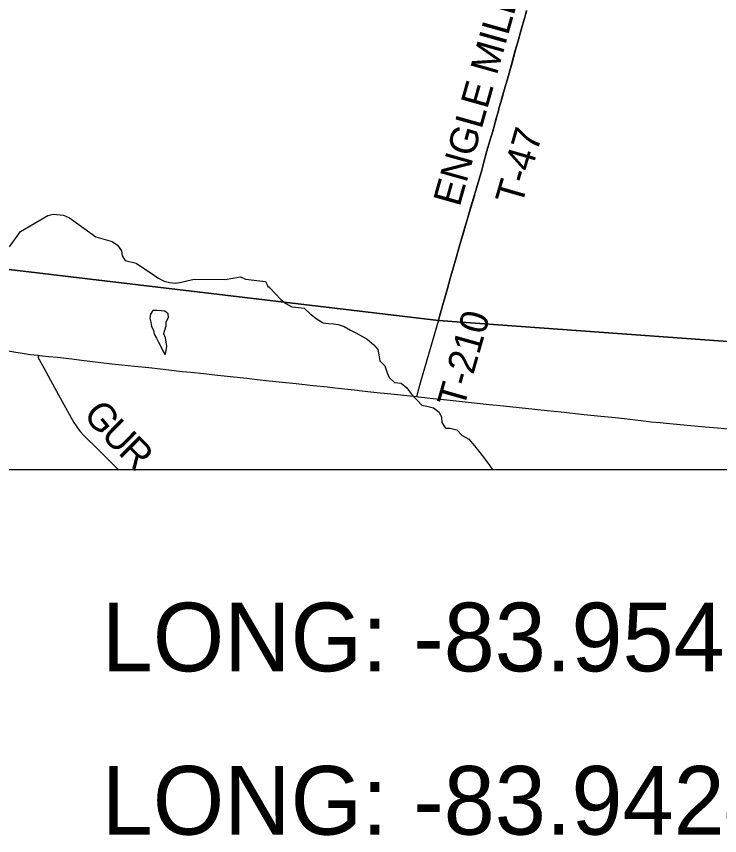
# Model space of a CAD drawing. Extents: x 0 to 34, y 0 to 22.
# Drawn here: x 12.815 to 14.248, y 13.559 to 15.23 of the extents above; entities that cross this region are included whole.
import ezdxf

# ---------------------------------------------------------------- set-up
doc = ezdxf.new("R2010")
doc.units = 0
for name, color, linetype in [('GM_X_Corporation', 7, 'Continuous'), ('GM_X_County_Road', 7, 'Continuous'), ('GM_X_County_Road_Text', 7, 'Continuous'), ('GM_X_Minor_Lake', 7, 'Continuous'), ('GM_X_Minor_River', 7, 'Continuous'), ('GM_X_Township_Road', 7, 'Continuous'), ('GM_X_Township_Road_Text', 7, 'Continuous'), ('SH_Text', 7, 'Continuous')]:
    doc.layers.add(name, color=color, linetype=linetype)

msp = doc.modelspace()

# ---------------------------------------------------------------- linework, layer by layer
at = {"layer": 'GM_X_Corporation'}
for points in [[(16.3375, 14.3932), (16.3375, 21.1059), (9.5375, 21.1059), (9.5375, 15.0426), (9.5452, 15.0418), (9.7185, 15.0258), (10.2502, 14.9799), (10.3112, 14.9746), (10.787, 14.9212), (11.3129, 14.8754), (11.3292, 14.8742), (12.1361, 14.7923), (13.6754, 14.6095), (14.714, 14.5341), (15.778, 14.4476), (16.0263, 14.4243)], [(10.7302, 14.3059), (16.3375, 14.3059), (16.3375, 14.3932), (16.0263, 14.4243), (15.778, 14.4476), (14.714, 14.5341), (13.6754, 14.6095), (12.1361, 14.7923), (11.3292, 14.8742), (11.3129, 14.8754), (10.787, 14.9212)], [(10.7302, 14.3059), (15.7632, 14.3059), (15.778, 14.4476), (14.714, 14.5341), (13.6754, 14.6095), (12.1361, 14.7923), (11.3292, 14.8742), (11.3129, 14.8754), (10.787, 14.9212)]]:
    msp.add_lwpolyline(points, close=True, dxfattribs=at)
for points in [[(12.1361, 14.7923), (13.6754, 14.6095), (13.6783, 14.6204), (13.6938, 14.6747), (13.6993, 14.6952), (13.7114, 14.7375), (13.717, 14.7569), (13.7274, 14.7926), (13.7338, 14.8149), (13.7418, 14.8415), (13.7492, 14.866), (13.7531, 14.8798), (13.7582, 14.8977), (13.7636, 14.9165), (13.7679, 14.9324), (13.7741, 14.9554), (13.7802, 14.976), (13.7861, 14.9957), (13.7895, 15.0079), (13.7928, 15.0196), (13.7976, 15.0375), (13.7988, 15.0419), (13.7995, 15.0445), (13.8005, 15.0482), (13.8016, 15.0517), (13.803, 15.0563), (13.8043, 15.0609), (13.8068, 15.0697), (13.8076, 15.0727), (13.8102, 15.0817), (13.8129, 15.0911), (13.8153, 15.0999), (13.8194, 15.1141), (13.8246, 15.1317), (13.8321, 15.1603), (13.8377, 15.1799), (13.8427, 15.1974), (13.8468, 15.2117), (13.8507, 15.2254), (13.8551, 15.2416)], [(13.8551, 15.2416), (13.8507, 15.2254), (13.8468, 15.2117), (13.8427, 15.1974), (13.8377, 15.1799), (13.8321, 15.1603), (13.8246, 15.1317), (13.8194, 15.1141), (13.8153, 15.0999), (13.8129, 15.0911), (13.8102, 15.0817), (13.8076, 15.0727), (13.8068, 15.0697), (13.8043, 15.0609), (13.803, 15.0563), (13.8016, 15.0517), (13.8005, 15.0482), (13.7995, 15.0445), (13.7988, 15.0419), (13.7976, 15.0375), (13.7928, 15.0196), (13.7895, 15.0079), (13.7861, 14.9957), (13.7802, 14.976), (13.7741, 14.9554), (13.7679, 14.9324), (13.7636, 14.9165), (13.7582, 14.8977), (13.7531, 14.8798), (13.7492, 14.866), (13.7418, 14.8415), (13.7338, 14.8149), (13.7274, 14.7926), (13.717, 14.7569), (13.7114, 14.7375), (13.6993, 14.6952), (13.6938, 14.6747), (13.6783, 14.6204), (13.6754, 14.6095), (14.714, 14.5341)]]:
    msp.add_lwpolyline(points, dxfattribs=at)
at = {"layer": 'GM_X_County_Road'}
for points in [[(12.6186, 14.5806), (12.6396, 14.5766), (12.6678, 14.5715), (12.702, 14.5654), (12.7197, 14.562), (12.7503, 14.5564), (12.8102, 14.546), (12.8317, 14.5423), (12.8434, 14.5405), (12.8595, 14.5387)], [(12.8595, 14.5387), (12.8625, 14.5383), (12.8811, 14.5364), (12.899, 14.5346), (12.9286, 14.5313), (12.9483, 14.529), (12.9876, 14.5242), (13.01, 14.5216), (13.0303, 14.5195), (13.0563, 14.5167), (13.0853, 14.5137), (13.1094, 14.5109), (13.1372, 14.5078), (13.1532, 14.506), (13.1711, 14.5041), (13.1977, 14.5013), (13.2255, 14.4983), (13.2848, 14.4919), (13.3058, 14.4897), (13.3305, 14.4868), (13.3508, 14.4845), (13.3855, 14.4809), (13.42, 14.4771), (13.4491, 14.4741), (13.4645, 14.4724), (13.5047, 14.4682), (13.5201, 14.4665), (13.538, 14.4645), (13.5565, 14.4625), (13.5652, 14.4615), (13.5856, 14.4593), (13.6177, 14.4559), (13.6312, 14.4545)], [(12.8595, 14.5387), (12.8599, 14.535), (12.8602, 14.5332), (12.8608, 14.5317), (12.8627, 14.5285), (12.8712, 14.5131), (12.8939, 14.4717), (12.9121, 14.4385), (12.9265, 14.4124), (12.9328, 14.4017), (12.9371, 14.395), (12.9414, 14.3889), (12.9464, 14.3826), (12.9525, 14.3757), (12.9612, 14.3669), (12.9745, 14.3538), (12.9963, 14.3325), (13.0227, 14.3059)], [(13.6312, 14.4545), (13.635, 14.4541), (13.6646, 14.4508), (13.6992, 14.4471), (13.7486, 14.4417), (13.7789, 14.4385), (13.8079, 14.4355), (13.8722, 14.4289), (13.8969, 14.4262), (13.9253, 14.4232), (13.9722, 14.4182), (14.0062, 14.4148), (14.0365, 14.4117), (14.0538, 14.4098), (14.0883, 14.4057), (14.1093, 14.4033), (14.1272, 14.4014), (14.1396, 14.4003), (14.1538, 14.3989), (14.1897, 14.3956), (14.2188, 14.3932), (14.2448, 14.3909), (14.2652, 14.389)]]:
    msp.add_lwpolyline(points, dxfattribs=at)
at = {"layer": 'GM_X_Minor_Lake'}
for points in [[(13.1168, 14.5859), (13.1206, 14.5989), (13.1204, 14.6073), (13.1251, 14.6155), (13.1245, 14.6231), (13.1178, 14.6286), (13.1102, 14.6295), (13.1019, 14.6304), (13.0935, 14.6302), (13.0888, 14.6223), (13.0871, 14.6144), (13.0892, 14.606), (13.091, 14.5983), (13.0946, 14.5892), (13.096, 14.5819)], [(13.096, 14.5819), (13.1008, 14.5735), (13.1048, 14.5658), (13.1099, 14.5566), (13.1139, 14.5481), (13.1187, 14.5397), (13.1208, 14.5487), (13.1217, 14.5571), (13.1207, 14.5658), (13.119, 14.5746), (13.1157, 14.5823), (13.1168, 14.5859)]]:
    msp.add_lwpolyline(points, dxfattribs=at)
at = {"layer": 'GM_X_Minor_River'}
for points in [[(12.8017, 14.7599), (12.8236, 14.791), (12.8793, 14.8235), (12.8904, 14.8263), (12.9112, 14.8246), (12.924, 14.819), (12.977, 14.7802), (13.0106, 14.7706), (13.0218, 14.7631), (13.0299, 14.7515), (13.0309, 14.7416), (13.0371, 14.732), (13.0598, 14.7265), (13.0971, 14.7016)], [(13.0971, 14.7016), (13.104, 14.6969), (13.1164, 14.6902), (13.1277, 14.6873), (13.1394, 14.6859), (13.1516, 14.6876), (13.1653, 14.6911), (13.1753, 14.6935), (13.1804, 14.6941)], [(13.1804, 14.6941), (13.2412, 14.6934), (13.272, 14.6987), (13.2822, 14.6939), (13.3234, 14.6892), (13.3273, 14.6808)], [(13.3266, 14.6808), (13.3321, 14.6764), (13.3433, 14.664), (13.3544, 14.6524), (13.3645, 14.6442), (13.3769, 14.6375), (13.3902, 14.6361), (13.4019, 14.6347), (13.4142, 14.6234), (13.4284, 14.6125), (13.4408, 14.6051), (13.4514, 14.6037), (13.4616, 14.6027), (13.4715, 14.6014), (13.4832, 14.5977), (13.496, 14.5903), (13.5072, 14.5847), (13.5208, 14.5772), (13.5305, 14.5717), (13.544, 14.5604), (13.5521, 14.5504), (13.5538, 14.5397), (13.5558, 14.5272), (13.5663, 14.5171), (13.5713, 14.5033), (13.5753, 14.4937), (13.5861, 14.4832), (13.5997, 14.4822), (13.6109, 14.4725), (13.6202, 14.4605), (13.6306, 14.4489), (13.6418, 14.4373), (13.652, 14.4348), (13.6656, 14.4319), (13.6772, 14.4229), (13.6819, 14.4126), (13.6824, 14.4019), (13.6902, 14.3904), (13.6997, 14.3902), (13.7133, 14.3865), (13.7237, 14.3753), (13.7376, 14.3674), (13.7491, 14.3542), (13.7569, 14.3442), (13.7643, 14.3342), (13.7754, 14.3199), (13.785, 14.3068), (13.7854, 14.3059)]]:
    msp.add_lwpolyline(points, dxfattribs=at)
at = {"layer": 'GM_X_Township_Road'}
for points in [[(13.8504, 15.223), (13.8509, 15.2248), (13.8553, 15.241)], [(13.6756, 14.6089), (13.6785, 14.6198), (13.6941, 14.6742), (13.6995, 14.6946), (13.7116, 14.737), (13.7172, 14.7563), (13.7276, 14.7921), (13.734, 14.8144), (13.742, 14.841), (13.7495, 14.8655), (13.7534, 14.8793), (13.7585, 14.8972), (13.7638, 14.9159), (13.7681, 14.9318), (13.7743, 14.9548), (13.7805, 14.9755), (13.7863, 14.9952), (13.7898, 15.0074), (13.7931, 15.0191), (13.7979, 15.0369), (13.7991, 15.0414), (13.7997, 15.044), (13.8007, 15.0476), (13.8018, 15.0512), (13.8032, 15.0558), (13.8046, 15.0603), (13.8071, 15.0692), (13.8079, 15.0722), (13.8104, 15.0812), (13.8131, 15.0905), (13.8155, 15.0994), (13.8196, 15.1136), (13.8248, 15.1311), (13.8323, 15.1597), (13.8379, 15.1794), (13.8429, 15.1969), (13.847, 15.2112), (13.8504, 15.223)], [(13.6312, 14.4545), (13.6355, 14.4704), (13.6398, 14.4854), (13.6511, 14.5248), (13.6727, 14.5997), (13.6756, 14.6089)]]:
    msp.add_lwpolyline(points, dxfattribs=at)

# ---------------------------------------------------------------- texts
at = {"layer": 'GM_X_County_Road_Text'}
for s, rotation, p in [('G', 309.2165, (12.9498, 14.4176)), ('U', 315.1567, (12.9857, 14.3741)), ('R', 314.9338, (13.0211, 14.3389))]:
    msp.add_text(s, height=0.0568, rotation=rotation, dxfattribs=at).set_placement(p)
at = {"layer": 'GM_X_Township_Road_Text'}
for s, height, rotation, p in [('ENGLE MILL RD', 0.056818, 74.2509, (13.7186, 14.8399)), ('T-47', 0.05682, 73.9092, (13.845, 14.8421)), ('T-210', 0.05682, 74.1322, (13.7269, 14.4287))]:
    msp.add_text(s, height=height, rotation=rotation, dxfattribs=at).set_placement(p)
at = {"layer": 'SH_Text'}
for s, p in [('LONG: -83.954278', (12.9893, 13.8943)), ('LONG: -83.942428', (12.9893, 13.5613))]:
    msp.add_text(s, height=0.14, dxfattribs=at).set_placement(p)

doc.saveas('drawing.dxf')
